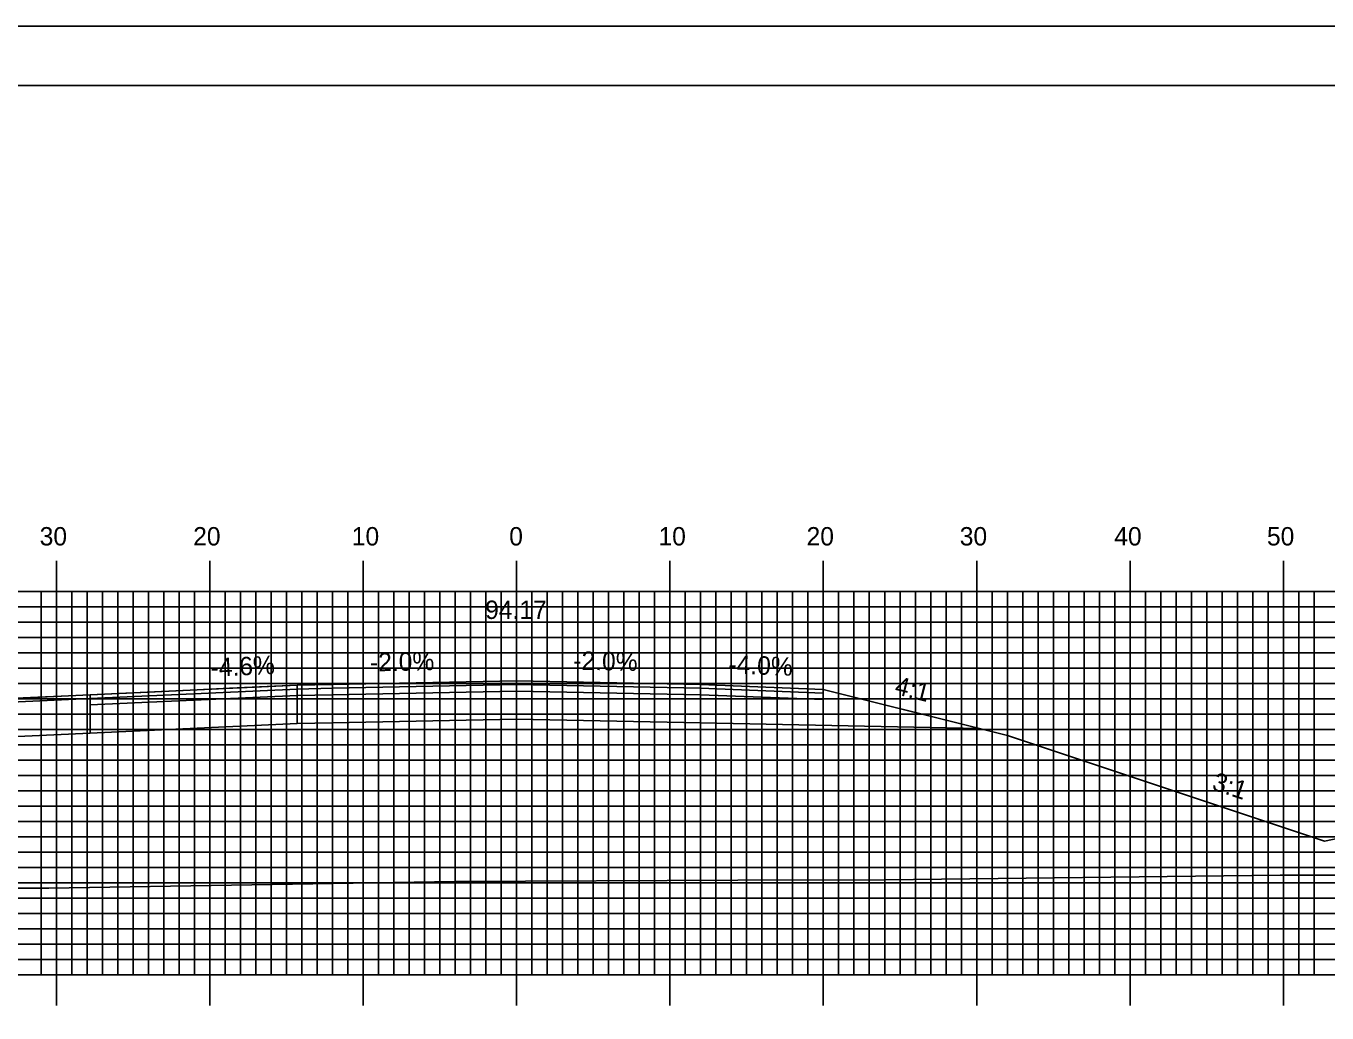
# Model space of a CAD drawing. Extents: x 1757069 to 1757412, y 442591 to 442811.
# Drawn here: x 1757202.6 to 1757287.4, y 442746.2 to 442810.5 of the extents above; entities that cross this region are included whole.
import ezdxf

# ---------------------------------------------------------------- set-up
doc = ezdxf.new("R2010")
doc.units = 0
for name, color, linetype in [('ANNOTATION', 7, 'Continuous'), ('BORDER', 7, 'Continuous'), ('D_Roadway_Centerline', 7, 'Continuous'), ('D_Roadway_Centerline_Text', 7, 'Continuous'), ('D_Roadway_Edge_Shoulder', 7, 'Continuous'), ('D_Roadway_Edge_TW', 7, 'Continuous'), ('D_Roadway_Pavement', 7, 'Continuous'), ('D_Roadway_SlopeLines', 7, 'Continuous'), ('D_Roadway_SubGrade', 7, 'Continuous'), ('H_V ANNOTATION', 7, 'Continuous'), ('MAJOR', 7, 'Continuous'), ('MINOR', 7, 'Continuous'), ('PLOT BOUNDARY', 7, 'Continuous'), ('S_Roadway_Centerline', 7, 'Continuous')]:
    doc.layers.add(name, color=color, linetype=linetype)

msp = doc.modelspace()

# ---------------------------------------------------------------- linework, layer by layer
at = {"layer": 'BORDER'}
msp.add_lwpolyline([(1757084.996, 442596.665), (1757404.996, 442596.665), (1757404.996, 442806.665), (1757084.996, 442806.665)], close=True, dxfattribs=at)
at = {"layer": 'D_Roadway_Centerline'}
for points in [[(1757200.457, 442766.639), (1757203.379, 442766.774), (1757204.888, 442766.843), (1757206.791, 442766.931), (1757210.566, 442767.105), (1757213.765, 442767.252), (1757215.875, 442767.35), (1757220.281, 442767.553), (1757222.596, 442767.599), (1757234.596, 442767.839), (1757246.596, 442767.599), (1757254.596, 442767.279), (1757264.77, 442764.736), (1757266.596, 442764.279), (1757287.283, 442757.383)], [(1757287.283, 442757.383), (1757289.482, 442757.845)]]:
    msp.add_lwpolyline(points, dxfattribs=at)
at = {"layer": 'D_Roadway_Edge_Shoulder'}
for points in [[(1757246.596, 442767.599), (1757254.596, 442767.279), (1757254.596, 442767.029), (1757246.596, 442767.349)], [(1757206.791, 442766.931), (1757195.521, 442766.411), (1757195.521, 442766.161), (1757206.791, 442766.681)]]:
    msp.add_lwpolyline(points, close=True, dxfattribs=at)
at = {"layer": 'D_Roadway_Edge_TW'}
for points in [[(1757222.596, 442767.599), (1757220.281, 442767.553), (1757220.281, 442767.303), (1757222.596, 442767.349)], [(1757222.596, 442767.349), (1757222.596, 442767.599), (1757234.596, 442767.839), (1757246.596, 442767.599), (1757246.596, 442767.349), (1757234.596, 442767.589)], [(1757220.281, 442767.553), (1757206.791, 442766.931), (1757206.791, 442766.681), (1757220.281, 442767.303)]]:
    msp.add_lwpolyline(points, close=True, dxfattribs=at)
msp.add_lwpolyline([(1757220.281, 442767.553), (1757220.281, 442767.303)], dxfattribs=at)
at = {"layer": 'D_Roadway_Pavement'}
for points in [[(1757222.596, 442766.932), (1757222.596, 442767.349), (1757234.596, 442767.589), (1757246.596, 442767.349), (1757246.596, 442766.932), (1757234.596, 442767.172)], [(1757220.281, 442767.303), (1757206.791, 442766.681), (1757206.791, 442766.264), (1757220.281, 442766.886)], [(1757222.596, 442767.349), (1757220.281, 442767.303), (1757220.281, 442766.886), (1757222.596, 442766.932)], [(1757246.596, 442767.349), (1757254.596, 442767.029), (1757254.596, 442766.612), (1757246.596, 442766.932)]]:
    msp.add_lwpolyline(points, close=True, dxfattribs=at)
for points in [[(1757220.281, 442767.303), (1757220.281, 442766.886)], [(1757220.281, 442767.303), (1757220.281, 442766.886)], [(1757206.791, 442766.681), (1757206.791, 442766.264)]]:
    msp.add_lwpolyline(points, dxfattribs=at)
at = {"layer": 'D_Roadway_SlopeLines'}
msp.add_lwpolyline([(1757254.596, 442767.279), (1757266.596, 442764.279), (1757287.283, 442757.383)], dxfattribs=at)
at = {"layer": 'D_Roadway_SubGrade'}
for points in [[(1757220.281, 442766.886), (1757206.791, 442766.264), (1757206.791, 442764.431), (1757220.281, 442765.053)], [(1757222.596, 442766.932), (1757220.281, 442766.886), (1757220.281, 442765.053), (1757222.596, 442765.099)], [(1757222.596, 442765.099), (1757222.596, 442766.932), (1757234.596, 442767.172), (1757246.596, 442766.932), (1757246.596, 442765.099), (1757234.596, 442765.339)], [(1757246.596, 442766.932), (1757254.596, 442766.612), (1757254.596, 442767.029), (1757254.596, 442767.279), (1757264.77, 442764.736), (1757246.596, 442765.099)], [(1757206.791, 442766.264), (1757206.791, 442766.681), (1757195.521, 442766.161), (1757195.521, 442766.411), (1757183.105, 442763.338), (1757206.791, 442764.431)]]:
    msp.add_lwpolyline(points, close=True, dxfattribs=at)
msp.add_lwpolyline([(1757220.281, 442766.886), (1757220.281, 442765.053)], dxfattribs=at)
at = {"layer": 'MAJOR'}
for p, q in [((1757204.596, 442775.669), (1757204.596, 442773.665)), ((1757214.596, 442775.669), (1757214.596, 442773.665)), ((1757224.596, 442775.669), (1757224.596, 442773.665)), ((1757234.596, 442775.669), (1757234.596, 442773.665)), ((1757244.596, 442775.669), (1757244.596, 442773.665)), ((1757254.596, 442775.669), (1757254.596, 442773.665)), ((1757264.596, 442775.669), (1757264.596, 442773.665)), ((1757274.596, 442775.669), (1757274.596, 442773.665)), ((1757284.596, 442775.669), (1757284.596, 442773.665)), ((1757094.596, 442773.665), (1757374.596, 442773.665)), ((1757094.596, 442773.665), (1757374.596, 442773.665)), ((1757204.596, 442748.665), (1757204.596, 442773.665)), ((1757214.596, 442748.665), (1757214.596, 442773.665)), ((1757224.596, 442748.665), (1757224.596, 442773.665)), ((1757234.596, 442748.665), (1757234.596, 442773.665)), ((1757244.596, 442748.665), (1757244.596, 442773.665)), ((1757254.596, 442748.665), (1757254.596, 442773.665)), ((1757264.596, 442748.665), (1757264.596, 442773.665)), ((1757274.596, 442748.665), (1757274.596, 442773.665)), ((1757284.596, 442748.665), (1757284.596, 442773.665)), ((1757094.596, 442768.665), (1757374.596, 442768.665)), ((1757094.596, 442763.665), (1757374.596, 442763.665)), ((1757094.596, 442758.665), (1757374.596, 442758.665)), ((1757094.596, 442753.665), (1757374.596, 442753.665)), ((1757094.596, 442748.665), (1757374.596, 442748.665)), ((1757094.596, 442748.665), (1757374.596, 442748.665)), ((1757204.596, 442746.661), (1757204.596, 442748.665)), ((1757214.596, 442746.661), (1757214.596, 442748.665)), ((1757224.596, 442746.661), (1757224.596, 442748.665)), ((1757234.596, 442746.661), (1757234.596, 442748.665)), ((1757244.596, 442746.661), (1757244.596, 442748.665)), ((1757254.596, 442746.661), (1757254.596, 442748.665)), ((1757264.596, 442746.661), (1757264.596, 442748.665)), ((1757274.596, 442746.661), (1757274.596, 442748.665)), ((1757284.596, 442746.661), (1757284.596, 442748.665))]:
    msp.add_line(p, q, dxfattribs=at)
at = {"layer": 'MINOR'}
for p, q in [((1757203.596, 442748.665), (1757203.596, 442773.665)), ((1757205.596, 442748.665), (1757205.596, 442773.665)), ((1757206.596, 442748.665), (1757206.596, 442773.665)), ((1757207.596, 442748.665), (1757207.596, 442773.665)), ((1757208.596, 442748.665), (1757208.596, 442773.665)), ((1757209.596, 442748.665), (1757209.596, 442773.665)), ((1757210.596, 442748.665), (1757210.596, 442773.665)), ((1757211.596, 442748.665), (1757211.596, 442773.665)), ((1757212.596, 442748.665), (1757212.596, 442773.665)), ((1757213.596, 442748.665), (1757213.596, 442773.665)), ((1757215.596, 442748.665), (1757215.596, 442773.665)), ((1757216.596, 442748.665), (1757216.596, 442773.665)), ((1757217.596, 442748.665), (1757217.596, 442773.665)), ((1757218.596, 442748.665), (1757218.596, 442773.665)), ((1757219.596, 442748.665), (1757219.596, 442773.665)), ((1757220.596, 442748.665), (1757220.596, 442773.665)), ((1757221.596, 442748.665), (1757221.596, 442773.665)), ((1757222.596, 442748.665), (1757222.596, 442773.665)), ((1757223.596, 442748.665), (1757223.596, 442773.665)), ((1757225.596, 442748.665), (1757225.596, 442773.665)), ((1757226.596, 442748.665), (1757226.596, 442773.665)), ((1757227.596, 442748.665), (1757227.596, 442773.665)), ((1757228.596, 442748.665), (1757228.596, 442773.665)), ((1757229.596, 442748.665), (1757229.596, 442773.665)), ((1757230.596, 442748.665), (1757230.596, 442773.665)), ((1757231.596, 442748.665), (1757231.596, 442773.665)), ((1757232.596, 442748.665), (1757232.596, 442773.665)), ((1757233.596, 442748.665), (1757233.596, 442773.665)), ((1757235.596, 442748.665), (1757235.596, 442773.665)), ((1757236.596, 442748.665), (1757236.596, 442773.665)), ((1757237.596, 442748.665), (1757237.596, 442773.665)), ((1757238.596, 442748.665), (1757238.596, 442773.665)), ((1757239.596, 442748.665), (1757239.596, 442773.665)), ((1757240.596, 442748.665), (1757240.596, 442773.665)), ((1757241.596, 442748.665), (1757241.596, 442773.665)), ((1757242.596, 442748.665), (1757242.596, 442773.665)), ((1757243.596, 442748.665), (1757243.596, 442773.665)), ((1757245.596, 442748.665), (1757245.596, 442773.665)), ((1757246.596, 442748.665), (1757246.596, 442773.665)), ((1757247.596, 442748.665), (1757247.596, 442773.665)), ((1757248.596, 442748.665), (1757248.596, 442773.665)), ((1757249.596, 442748.665), (1757249.596, 442773.665)), ((1757250.596, 442748.665), (1757250.596, 442773.665)), ((1757251.596, 442748.665), (1757251.596, 442773.665)), ((1757252.596, 442748.665), (1757252.596, 442773.665)), ((1757253.596, 442748.665), (1757253.596, 442773.665)), ((1757255.596, 442748.665), (1757255.596, 442773.665)), ((1757256.596, 442748.665), (1757256.596, 442773.665)), ((1757257.596, 442748.665), (1757257.596, 442773.665)), ((1757258.596, 442748.665), (1757258.596, 442773.665)), ((1757259.596, 442748.665), (1757259.596, 442773.665)), ((1757260.596, 442748.665), (1757260.596, 442773.665)), ((1757261.596, 442748.665), (1757261.596, 442773.665)), ((1757262.596, 442748.665), (1757262.596, 442773.665)), ((1757263.596, 442748.665), (1757263.596, 442773.665)), ((1757265.596, 442748.665), (1757265.596, 442773.665)), ((1757266.596, 442748.665), (1757266.596, 442773.665)), ((1757267.596, 442748.665), (1757267.596, 442773.665)), ((1757268.596, 442748.665), (1757268.596, 442773.665)), ((1757269.596, 442748.665), (1757269.596, 442773.665)), ((1757270.596, 442748.665), (1757270.596, 442773.665)), ((1757271.596, 442748.665), (1757271.596, 442773.665)), ((1757272.596, 442748.665), (1757272.596, 442773.665)), ((1757273.596, 442748.665), (1757273.596, 442773.665)), ((1757275.596, 442748.665), (1757275.596, 442773.665)), ((1757276.596, 442748.665), (1757276.596, 442773.665)), ((1757277.596, 442748.665), (1757277.596, 442773.665)), ((1757278.596, 442748.665), (1757278.596, 442773.665)), ((1757279.596, 442748.665), (1757279.596, 442773.665)), ((1757280.596, 442748.665), (1757280.596, 442773.665)), ((1757281.596, 442748.665), (1757281.596, 442773.665)), ((1757282.596, 442748.665), (1757282.596, 442773.665)), ((1757283.596, 442748.665), (1757283.596, 442773.665)), ((1757285.596, 442748.665), (1757285.596, 442773.665)), ((1757286.596, 442748.665), (1757286.596, 442773.665)), ((1757094.596, 442772.665), (1757374.596, 442772.665)), ((1757094.596, 442771.665), (1757374.596, 442771.665)), ((1757094.596, 442770.665), (1757374.596, 442770.665)), ((1757094.596, 442769.665), (1757374.596, 442769.665)), ((1757094.596, 442767.665), (1757374.596, 442767.665)), ((1757094.596, 442766.665), (1757374.596, 442766.665)), ((1757094.596, 442765.665), (1757374.596, 442765.665)), ((1757094.596, 442764.665), (1757374.596, 442764.665)), ((1757094.596, 442762.665), (1757374.596, 442762.665)), ((1757094.596, 442761.665), (1757374.596, 442761.665)), ((1757094.596, 442760.665), (1757374.596, 442760.665)), ((1757094.596, 442759.665), (1757374.596, 442759.665)), ((1757094.596, 442757.665), (1757374.596, 442757.665)), ((1757094.596, 442756.665), (1757374.596, 442756.665)), ((1757094.596, 442755.665), (1757374.596, 442755.665)), ((1757094.596, 442754.665), (1757374.596, 442754.665)), ((1757094.596, 442752.665), (1757374.596, 442752.665)), ((1757094.596, 442751.665), (1757374.596, 442751.665)), ((1757094.596, 442750.665), (1757374.596, 442750.665)), ((1757094.596, 442749.665), (1757374.596, 442749.665))]:
    msp.add_line(p, q, dxfattribs=at)
at = {"layer": 'PLOT BOUNDARY'}
msp.add_lwpolyline([(1757068.809, 442590.547), (1757408.809, 442590.547), (1757408.809, 442810.547), (1757068.809, 442810.547)], close=True, dxfattribs=at)
at = {"layer": 'S_Roadway_Centerline'}
msp.add_lwpolyline([(1757094.596, 442753.699), (1757106.015, 442753.686), (1757125.799, 442753.961), (1757135.342, 442753.908), (1757159.115, 442753.837), (1757182.029, 442754.123), (1757202.034, 442754.311), (1757204.088, 442754.319), (1757230.574, 442754.748), (1757249.031, 442754.836), (1757258.631, 442754.858), (1757284.397, 442755.152), (1757295.54, 442755.166), (1757319.951, 442754.947), (1757333.06, 442754.892), (1757374.596, 442754.636)], dxfattribs=at)

# ---------------------------------------------------------------- texts
at = {"layer": 'ANNOTATION'}
for s, rotation, p in [('-4.6%', 2.63883, (1757214.665, 442768.096)), ('-2.0%', 1.14576, (1757225.045, 442768.448)), ('-2.0%', 358.85424, (1757238.282, 442768.566)), ('-4.0%', 357.70939, (1757248.388, 442768.329)), ('4:1', 345.96376, (1757259.189, 442766.992)), ('3:1', 341.56522, (1757279.872, 442760.762))]:
    msp.add_text(s, height=1.2, rotation=rotation, dxfattribs=at).set_placement(p)
at = {"layer": 'D_Roadway_Centerline'}
for s, p in [('C', (1757234.591, 442767.839)), ('L', (1757234.596, 442767.832))]:
    msp.add_text(s, height=0.0146, dxfattribs=at).set_placement(p)
at = {"layer": 'D_Roadway_Centerline_Text'}
msp.add_text('94.17', height=1.2, dxfattribs=at).set_placement((1757232.542, 442771.872))
at = {"layer": 'H_V ANNOTATION'}
for s, p in [('30', (1757203.493, 442776.665)), ('20', (1757213.504, 442776.665)), ('10', (1757223.847, 442776.665)), ('0', (1757234.114, 442776.665)), ('10', (1757243.847, 442776.665)), ('20', (1757253.504, 442776.665)), ('30', (1757263.493, 442776.665)), ('40', (1757273.568, 442776.665)), ('50', (1757283.525, 442776.665))]:
    msp.add_text(s, height=1.2, dxfattribs=at).set_placement(p)

doc.saveas('drawing.dxf')
